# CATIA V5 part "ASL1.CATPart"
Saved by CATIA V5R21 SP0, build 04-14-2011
Part number: ASL1.SLDPRT
Bounding box of the stored display mesh (mm): x -0.583 to 1.017, y -0.91 to 1.09, z 1.695 to 2.476
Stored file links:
  C:\Users\user\Desktop\CATIA文件\0-最新文件(2025.3月之前的慎用)\ASL1\ASL1.CATPart
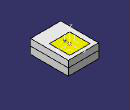
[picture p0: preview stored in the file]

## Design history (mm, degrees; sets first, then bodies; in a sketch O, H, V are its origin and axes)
AxisSystem1: origin (0.2168, 0.3595, 2.4755), X (1, 0, 0), Y (0, 1, 0), Z (0, 0, 1)
Set1
  DatumSurface1 to DatumSurface14
  Line1: stored without definition
  Circle1: stored without definition
  Line2: stored without definition
  Circle2: stored without definition
  Line3: stored without definition
  Circle3: stored without definition
  Line4: stored without definition
  Circle4: stored without definition
  Line5: stored without definition
  Circle5: stored without definition
  Line6: stored without definition
  Circle6: stored without definition
  Line7: stored without definition
  Circle7: stored without definition
  Line8: stored without definition
  Circle8: stored without definition
  Line9 to Line20: stored without definition
  Circle9 to Circle16: stored without definition
  DatumSurface15 to DatumSurface18
  Circle17: stored without definition
  Line21: stored without definition
  Circle18: stored without definition
  Line22: stored without definition
  Circle19: stored without definition
  Circle20: stored without definition
  DatumSurface19 to DatumSurface22
  Circle21: stored without definition
  Line23: stored without definition
  Circle22: stored without definition
  Line24: stored without definition
  Circle23: stored without definition
  Circle24: stored without definition
  DatumSurface23 to DatumSurface26
  Circle25: stored without definition
  Line25: stored without definition
  Circle26: stored without definition
  Line26: stored without definition
  Circle27: stored without definition
  Circle28: stored without definition
  DatumSurface27 to DatumSurface30
  Circle29: stored without definition
  Line27: stored without definition
  Circle30: stored without definition
  Line28: stored without definition
  Circle31: stored without definition
  Circle32: stored without definition
  DatumSurface31 to DatumSurface38
  Line29 to Line46: stored without definition
  DatumSurface39 to DatumSurface47
  Line47 to Line67: stored without definition
  DatumSurface48 to DatumSurface57
  Line68 to Line84: stored without definition
  Circle33 to Circle38: stored without definition
  Line85: stored without definition
  DatumSurface58 to DatumSurface67
  Line86 to Line101: stored without definition
  Circle39 to Circle46: stored without definition
  DatumSurface68 to DatumSurface77
  Line102 to Line117: stored without definition
  Circle47 to Circle54: stored without definition
  DatumSurface78 to DatumSurface83
  Line118 to Line129: stored without definition
  DatumSurface84 to DatumSurface93
  Line130 to Line153: stored without definition
  Point1 "发光中心（测试原点）": type Between, FirstPoint vertex [face of DatumSurface92], SecondPoint vertex [face of DatumSurface88], Ratio 0.5
  Point2 "几何中心": type Between, FirstPoint vertex [face of DatumSurface85], SecondPoint vertex [face of DatumSurface84], Ratio 0.5
  Point3 "虚拟坐标": (0.011, 0.004, -0.041), relative to Point1, in AxisSystem1
Body1 (main body)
